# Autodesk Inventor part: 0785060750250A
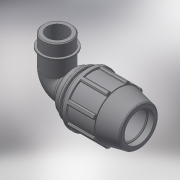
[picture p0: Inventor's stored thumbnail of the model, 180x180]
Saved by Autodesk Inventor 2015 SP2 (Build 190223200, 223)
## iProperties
Created: 2017-02
Part Number: 0785060750250A
Material: Generic
Description: PLASSON 90° ELBOW MALE ADAPTOR 75-2.1/2"
Document SubType Name: Modeling
Designer: KIM
Mass: 1366.09 g
Surface Area: 1816.46 cm^2
Volume: 1366.09 cm^3
Density: 1 g/cm^3
Appearance: Default
Author: KIM
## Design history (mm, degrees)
derived "87850.ipt"
feature "Solid1::87850.ipt"
tag "TaggingFeature1"
body "Solid1"
other parameters: "d2" = 75, "d4" = 16.83333, "d5" = 50.5, "d7" = 134, "d9" = 28.85714, "d11" = 6.73333, "d13" = 120 deg, "d14" = 97.5, "d15" = 12 deg, "d16" = 116.58, "d18" = 3.75, "d19" = 35 deg, "d20" = 17.5 deg, "d21" = 124.62, "d23" = 0, "d25" = 360 deg, "d27" = 2.68, "d33" = 1.5, "d42" = 74.74, "d43" = 4.02, "d46" = 2.25, "d51" = 202, "d68" = 13.46667, "d72" = 105, "d73" = 72.226, "d75" = 83.0599, "d76" = 50.5582, "d77" = 33, "d79" = 28.8904, "d80" = 2.16678, "d83" = 0, "d84" = 0, "d91" = 100.5, "d93" = 132, "d94" = 72.226, "d95" = 50.5582, "d96" = 13.46667, "d97" = 50 deg, "d98" = 3.36667, "d99" = 113.0826, "d100" = 3.36667, "d101" = 3.36667, "d102" = 8.93333, "d103" = 0, "d_" = 75, "E_" = 134, "A_" = 202, "l_" = 132, "A_1" = 105, "G_" = 72.226
